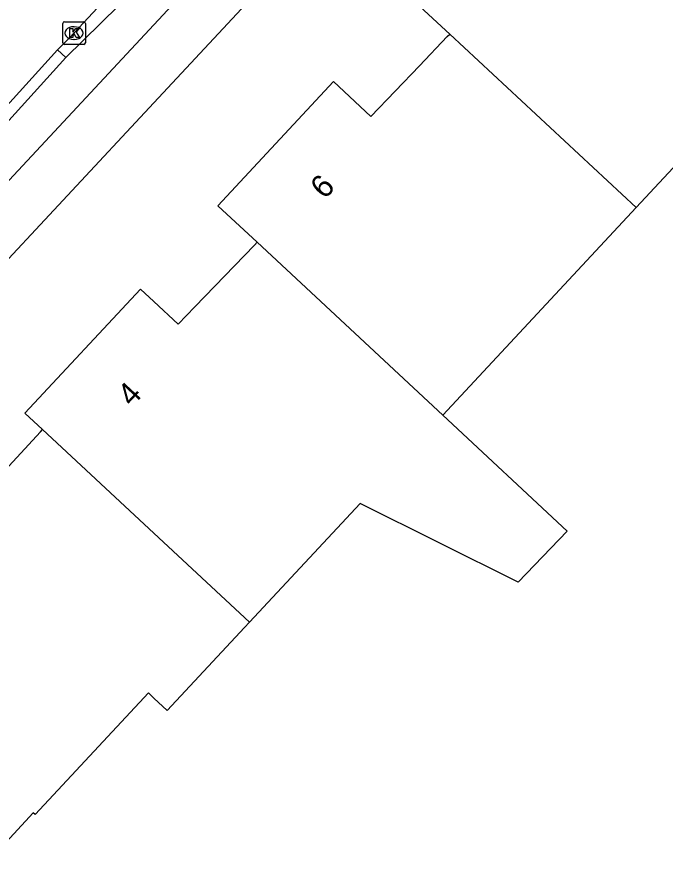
# Model space of a CAD drawing. Extents: x 159628 to 160723, y 388176 to 389416.
# Drawn here: x 160493.96 to 160522.54, y 388618.4 to 388655.56 of the extents above; entities that cross this region are included whole.
import ezdxf

# ---------------------------------------------------------------- set-up
doc = ezdxf.new("R2010")
doc.units = 0
for name, color, linetype in [('IMGEO_Fietspad_gesloten', 7, 'Continuous'), ('IMGEO_Kolk', 7, 'Continuous'), ('IMGEO_Pand', 7, 'Continuous'), ('IMGEO_Pand_nummerreeks', 7, 'Continuous'), ('IMGEO_Rijbaan_lokaal_gesloten', 7, 'Continuous'), ('IMGEO_Voetpad_open', 7, 'Continuous')]:
    doc.layers.add(name, color=color, linetype=linetype)

msp = doc.modelspace()

# ---------------------------------------------------------------- linework, layer by layer
at = {"layer": 'IMGEO_Fietspad_gesloten'}
for points in [[(160557.261, 388716.685), (160500, 388655.208), (160478.454, 388632.075)], [(160502.251, 388660.315), (160500, 388657.587), (160496.111, 388653.76)], [(160496.111, 388653.76), (160493.6, 388650.985)]]:
    msp.add_lwpolyline(points, dxfattribs=at)
at = {"layer": 'IMGEO_Kolk'}
for p, q in [((160496.052, 388655.337), (160496.904, 388655.337)), ((160495.977, 388654.411), (160495.977, 388655.263)), ((160496.465, 388655.117), (160496.49, 388655.117)), ((160496.978, 388655.263), (160496.978, 388654.411)), ((160496.904, 388654.337), (160496.052, 388654.337)), ((160496.488, 388654.557), (160496.463, 388654.557))]:
    msp.add_line(p, q, dxfattribs=at)
for points in [[(160496.052, 388655.337), (160496.904, 388655.337)], [(160495.977, 388654.411), (160495.977, 388655.263)], [(160496.298, 388655.037), (160496.421, 388655.037), (160496.421, 388654.886), (160496.551, 388655.037), (160496.715, 388655.037), (160496.569, 388654.886), (160496.722, 388654.637), (160496.57, 388654.637), (160496.485, 388654.801), (160496.421, 388654.734), (160496.421, 388654.637), (160496.298, 388654.637), (160496.298, 388655.037)], [(160496.978, 388655.263), (160496.978, 388654.411)], [(160496.904, 388654.337), (160496.052, 388654.337)]]:
    msp.add_lwpolyline(points, dxfattribs=at)
for centre, start, end in [((160496.054, 388655.261), 91.552, 178.448), ((160496.054, 388655.261), 91.552, 178.448), ((160496.902, 388655.261), 1.552, 88.448), ((160496.902, 388655.261), 1.552, 88.448), ((160496.054, 388654.413), 181.552, 268.448), ((160496.054, 388654.413), 181.552, 268.448), ((160496.902, 388654.413), 271.552, 358.448), ((160496.902, 388654.413), 271.552, 358.448)]:
    msp.add_arc(centre, 0.0765, start, end, dxfattribs=at)
for centre, major_axis, ratio, start_param, end_param in [((160496.464, 388654.837), (-0.387, 0.002), 0.722429, 4.712389, 7.853982), ((160496.489, 388654.837), (-0.39, 0.002), 0.717154, 1.570796, 4.712389)]:
    msp.add_ellipse(centre, major_axis=major_axis, ratio=ratio, start_param=start_param, end_param=end_param, dxfattribs=at)
at = {"layer": 'IMGEO_Pand'}
for points in [[(160513.046, 388654.798), (160511.348, 388656.381), (160516.436, 388661.858), (160518.136, 388660.237), (160519.129, 388661.315), (160521.439, 388663.824), (160521.558, 388663.953)], [(160529.782, 388656.292), (160521.257, 388647.14)], [(160504.551, 388645.612), (160502.822, 388647.223), (160507.925, 388652.71), (160509.568, 388651.164), (160511.707, 388653.399), (160512.934, 388654.681), (160513.046, 388654.798)], [(160513.046, 388654.798), (160521.257, 388647.14)], [(160521.257, 388647.14), (160512.732, 388637.988)], [(160495.089, 388637.345), (160494.311, 388638.07), (160499.414, 388643.547), (160500, 388643.003), (160501.075, 388642.004), (160501.798, 388642.755), (160504.429, 388645.486), (160504.551, 388645.612)], [(160512.732, 388637.988), (160504.551, 388645.612)], [(160512.732, 388637.988), (160518.223, 388632.87), (160516.056, 388630.62), (160509.098, 388634.087), (160504.214, 388628.844)], [(160504.214, 388628.844), (160503.997, 388628.611), (160500.588, 388624.952), (160500, 388625.5), (160499.754, 388625.729), (160494.759, 388620.367), (160494.682, 388620.439), (160492.774, 388618.395), (160489.119, 388621.807), (160491.012, 388623.835), (160488.444, 388626.213), (160484.789, 388629.625), (160490.007, 388635.212), (160491.678, 388633.665), (160495.001, 388637.25), (160495.089, 388637.345)], [(160504.214, 388628.844), (160500, 388632.77), (160495.089, 388637.345)]]:
    msp.add_lwpolyline(points, dxfattribs=at)
at = {"layer": 'IMGEO_Rijbaan_lokaal_gesloten'}
for points in [[(160495.741, 388654.095), (160496.284, 388654.631), (160500, 388658.627), (160501.89, 388660.659)], [(160493.23, 388651.32), (160495.741, 388654.095)]]:
    msp.add_lwpolyline(points, dxfattribs=at)
at = {"layer": 'IMGEO_Voetpad_open'}
for points in [[(160480.943, 388631.314), (160500, 388651.764), (160560.212, 388716.376)], [(160495.741, 388654.095), (160496.111, 388653.76)]]:
    msp.add_lwpolyline(points, dxfattribs=at)

# ---------------------------------------------------------------- texts
at = {"layer": 'IMGEO_Pand_nummerreeks'}
for s, rotation, p in [('6', 47.0742, (160507.532, 388647.472)), ('4', 47.0226, (160499.021, 388638.313))]:
    msp.add_text(s, height=1, rotation=rotation, dxfattribs=at).set_placement(p)

doc.saveas('drawing.dxf')
